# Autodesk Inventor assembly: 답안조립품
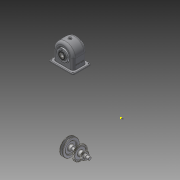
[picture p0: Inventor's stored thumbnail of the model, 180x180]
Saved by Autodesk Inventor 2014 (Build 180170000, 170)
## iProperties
Created: 2016-02
Part Number: 답안조립품
Document SubType Name: Assembly
Designer: Owner
Author: Owner
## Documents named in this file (14)
- C:\Documents and Settings\Owner\바탕 화면\460105V1002\답안조립품.iam
- C:\Documents and Settings\Owner\바탕 화면\460105V1002\본체.ipt
- C:\Documents and Settings\Owner\바탕 화면\460105V1002\오일씰 28 40 8.ipt
- C:\Documents and Settings\Owner\바탕 화면\460105V1002\뒤커버.ipt
- C:\Documents and Settings\Owner\바탕 화면\460105V1002\베어링 6203.ipt
- C:\Documents and Settings\Owner\바탕 화면\460105V1002\앞커버.ipt
- C:\Documents and Settings\Owner\바탕 화면\460105V1002\V-벨트풀리.ipt
- C:\Documents and Settings\Owner\바탕 화면\460105V1002\부시1.ipt
- C:\Documents and Settings\Owner\바탕 화면\460105V1002\부시2.ipt
- C:\Documents and Settings\Owner\바탕 화면\460105V1002\스퍼기어.ipt
- C:\Documents and Settings\Owner\바탕 화면\460105V1002\축.ipt
- C:\Documents and Settings\Owner\바탕 화면\460105V1002\키 - 6 x 6 x 22.ipt
- C:\Documents and Settings\Owner\바탕 화면\460105V1002\키 - 5 x 5 x 18.ipt
- C:\Documents and Settings\Owner\바탕 화면\460105V1002\멈춤나사 - M4x10.ipt
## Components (1 placed, 1 different names)
1. V-벨트풀리:1 — 각도:4
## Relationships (1: Angle 1)
- 각도:4 [Angle]: V-벨트풀리:1
